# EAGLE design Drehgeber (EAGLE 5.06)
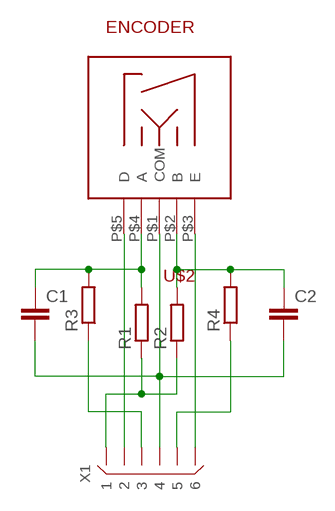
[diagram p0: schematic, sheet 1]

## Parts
C1  C-EU025-025X050  [C025-025X050]
C2  C-EU025-025X050  [C025-025X050]
R1  R-EU_0207/7  [0207/7]
R2  R-EU_0207/7  [0207/7]
R3  R-EU_0207/7  [0207/7]
R4  R-EU_0207/7  [0207/7]
U$2  ENCODER  [ENCODER]
X1  X06L  [X06L-SIL]

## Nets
N$1: C1.1 R1.2 R3.2 U$2.P$4(A)
N$2: C2.1 R2.2 R4.2 U$2.P$2(B)
N$3: R1.1 R2.1 X1.1
N$4: R3.1 X1.3
N$5: R4.1 X1.5
N$6: C1.2 C2.2 U$2.P$1(COM) X1.4
N$7: U$2.P$5(D) X1.2
N$9: U$2.P$3(E) X1.6

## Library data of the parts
C1 C2 = rcl:C-EU: CAPACITOR, European symbol
R1-R4 = resistor:R-EU_: RESISTOR, European symbol
U$2 = panasonic:ENCODER
X1 = connectors:X06: Connector 6 pins

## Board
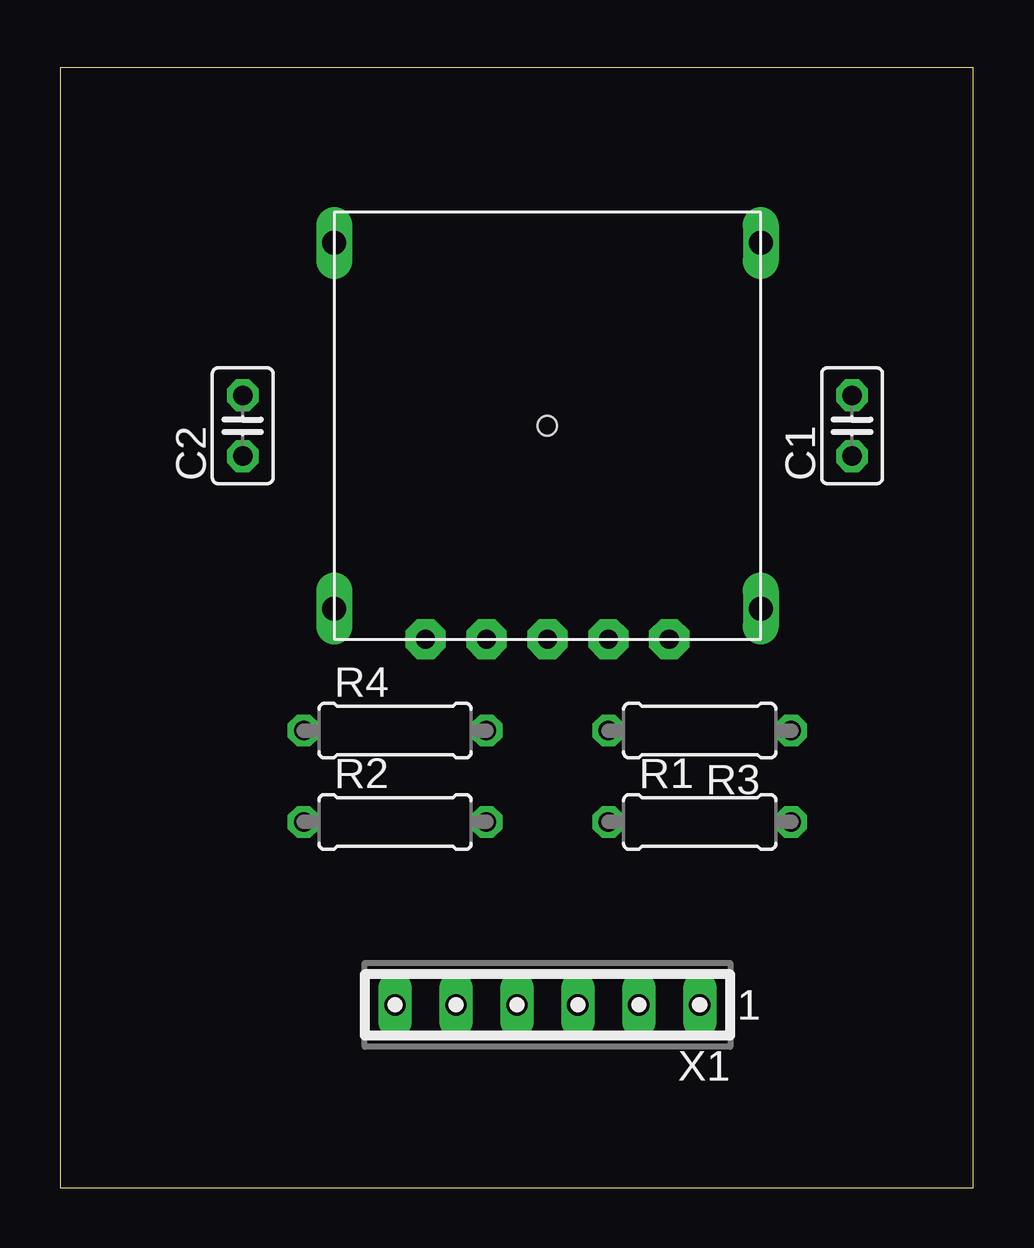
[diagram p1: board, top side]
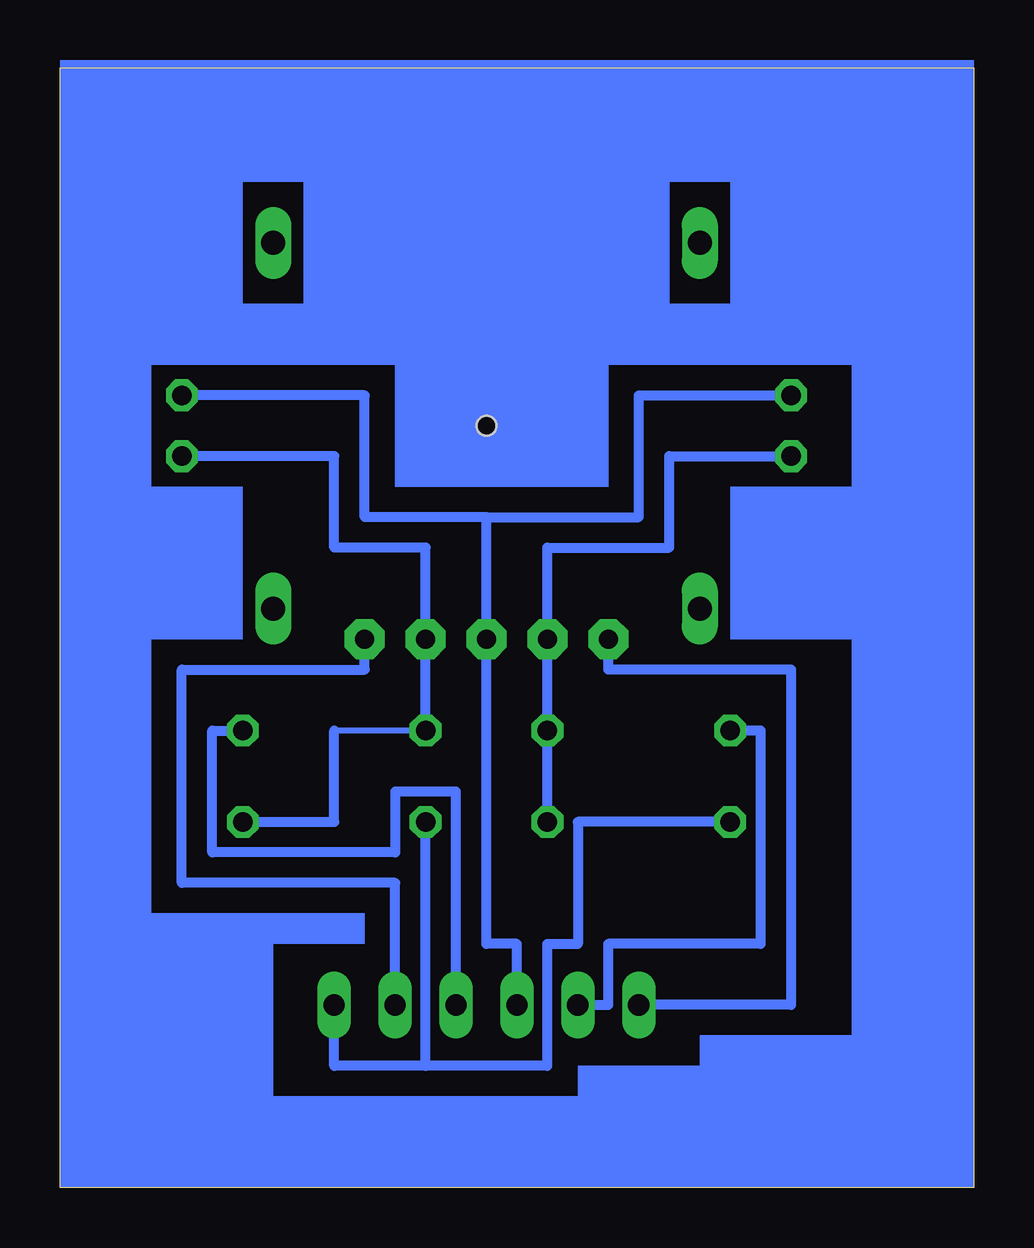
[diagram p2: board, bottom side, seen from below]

Size 38.08 x 46.66 mm. Coordinates in mm from the lower left corner, seen from the top.
Outline: 0,0 38.08,0 38.08,46.66 0,46.66 0,0
Copper layers (1*16): Top 0.035mm / dielectric 1.5mm / Bottom 0.035mm
Design rules "default": minimum track width 10mil, minimum drill 24mil, track to track 8mil, track to pad 8mil, pad to pad 8mil, via to via 8mil, smd to smd 8mil, copper to edge 40mil, drill to drill 8mil, minimum pad ring 10mil, minimum via ring 8mil, stop-mask expansion 4mil, vias tented up to drill 0mil, thermal gap 10mil

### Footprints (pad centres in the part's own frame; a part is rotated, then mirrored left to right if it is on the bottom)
C025-025X050 = drill 0.813 octagon: 1 -1.27,0; 2 1.27,0
0207/7 = drill 0.813 octagon: 1 -3.81,0; 2 3.81,0
ENCODER = drill 0.8 pad 1.676 octagon: P$1 0,8.89; P$2 2.54,8.89; P$3 5.08,8.89; P$4 -2.54,8.89; P$5 -5.08,8.89 | drill 1 pad 1.422 long: P$6 -8.89,7.62; P$7 8.89,7.62; P$8 -8.89,-7.62; P$9 8.89,-7.62 | hole 0.8: 0,0
X06L-SIL = drill 0.889 pad 1.397 long: 1 -6.35,0; 2 -3.81,0; 3 -1.27,0; 4 1.27,0; 5 3.81,0; 6 6.35,0

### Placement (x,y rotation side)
C1  33.02,31.75 90 top
C2  7.62,31.75 90 top
R1  26.67,15.24 0 top
R2  13.97,15.24 0 top
R3  26.67,19.05 180 top
R4  13.97,19.05 0 top
U$2  20.32,31.75 180 top
X1  20.32,7.62 180 top

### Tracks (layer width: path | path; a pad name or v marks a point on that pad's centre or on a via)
N$1
  Bottom 0.254: R3.2 26.67,19.05
  Bottom 0.406: C1.1 26.67,30.48 26.67,26.67 22.86,26.67 U$2.P$4 R3.2 | R1.2 26.67,15.24 26.67,19.05
N$2
  Bottom 0.406: C2.1 12.7,30.48 12.7,26.67 17.78,26.67 U$2.P$2 R4.2 R2.2
N$3
  Bottom 0.406: 22.86,5.08 26.67,5.08 X1.1 | 22.86,5.08 17.78,5.08 17.78,10.16 16.51,10.16 16.51,15.24 R2.1 | 22.86,5.08 R1.1
N$4
  Bottom 0.406: R3.1 31.75,19.05 31.75,13.97 24.13,13.97 24.13,16.51 21.59,16.51 X1.3
N$5
  Bottom 0.406: R4.1 8.89,19.05 8.89,10.16 15.24,10.16 15.24,7.62 X1.5
N$6
  Bottom 0.406: C2.2 13.97,33.02 13.97,27.94 20.32,27.94 | 20.32,27.94 U$2.P$1 20.32,10.16 19.05,10.16 X1.4 | C1.2 25.4,33.02 25.4,27.94 20.32,27.94
N$7
  Bottom 0.406: X1.2 24.13,12.7 33.02,12.7 33.02,21.59 25.4,21.59 U$2.P$5
N$9
  Bottom 0.406: U$2.P$3 15.24,21.59 7.62,21.59 7.62,7.62 X1.6
(copper drawn outside any net)
  shapes: Bottom area x19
